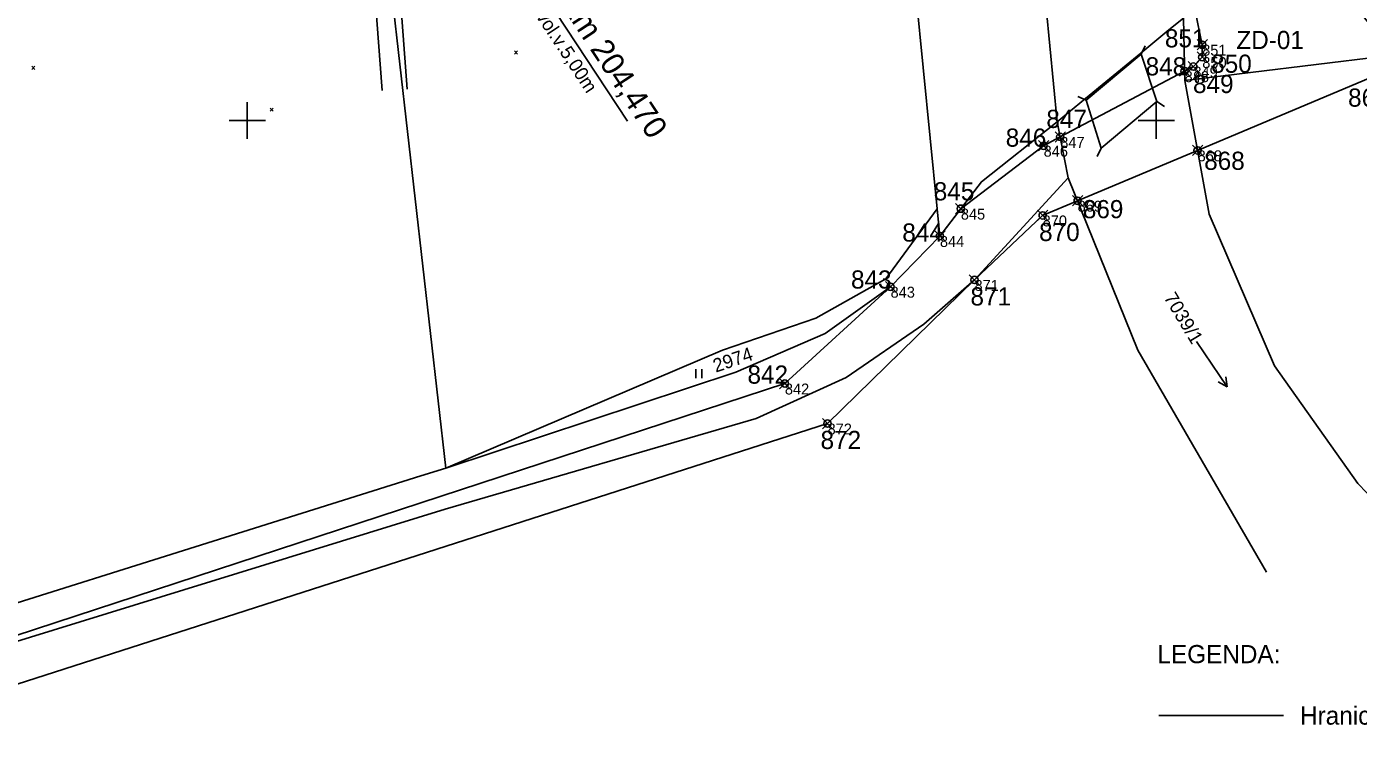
# Model space of a CAD drawing. Extents: x -800194 to -799078, y -1007177 to -1006597.
# Drawn here: x -799524.3 to -799377.8, y -1007068 to -1006989.7 of the extents above; entities that cross this region are included whole.
import ezdxf

# ---------------------------------------------------------------- set-up
doc = ezdxf.new("R2010")
doc.units = 0
for name, color, linetype in [('02_Osa_koleje', 7, 'Continuous'), ('Dočasné zábory', 7, 'Continuous'), ('Dočasné zábory - čísla', 7, 'Continuous'), ('Legenda', 7, 'Continuous'), ('Ramove udaje', 7, 'Continuous'), ('Vrstva 18', 7, 'Continuous'), ('Vrstva 49', 7, 'Continuous'), ('Vrstva 51', 7, 'Continuous'), ('Vrstva 53', 7, 'Continuous'), ('Vrstva 55', 7, 'Continuous'), ('Vrstva 56', 7, 'Continuous'), ('Vrstva 57', 7, 'Continuous'), ('Vrstva 58', 7, 'Continuous'), ('Vrstva 60', 7, 'Continuous')]:
    doc.layers.add(name, color=color, linetype=linetype)

msp = doc.modelspace()

# ---------------------------------------------------------------- linework, layer by layer
at = {"layer": '02_Osa_koleje'}
msp.add_arc((-799651.02, -1006703.89), 292, 255.6249, 308.2052, dxfattribs=at)
at = {"layer": 'Dočasné zábory'}
for p, q in [((-799395.51, -1006992.22), (-799394.38, -1006991.09)), ((-799395.51, -1006991.09), (-799394.38, -1006992.22)), ((-799395.51, -1006993.59), (-799394.37, -1006992.46)), ((-799395.51, -1006992.46), (-799394.37, -1006993.59)), ((-799397.45, -1006995.14), (-799396.32, -1006994.01)), ((-799397.45, -1006994.01), (-799396.32, -1006995.14)), ((-799396.49, -1006994.64), (-799395.36, -1006993.51)), ((-799396.49, -1006993.51), (-799395.36, -1006994.64)), ((-799411.13, -1007002.37), (-799410, -1007001.24)), ((-799411.13, -1007001.24), (-799410, -1007002.37)), ((-799412.96, -1007003.34), (-799411.83, -1007002.21)), ((-799412.96, -1007002.21), (-799411.83, -1007003.34)), ((-799396.02, -1007003.85), (-799394.89, -1007002.72)), ((-799396.02, -1007002.72), (-799394.89, -1007003.85)), ((-799409.22, -1007009.4), (-799408.09, -1007008.26)), ((-799409.22, -1007008.26), (-799408.09, -1007009.4)), ((-799422.07, -1007010.27), (-799420.94, -1007009.14)), ((-799422.07, -1007009.14), (-799420.94, -1007010.27)), ((-799413.06, -1007011.01), (-799411.93, -1007009.88)), ((-799413.06, -1007009.88), (-799411.93, -1007011.01)), ((-799424.37, -1007013.28), (-799423.23, -1007012.14)), ((-799424.37, -1007012.14), (-799423.23, -1007013.28)), ((-799429.8, -1007018.86), (-799428.66, -1007017.72)), ((-799429.8, -1007017.72), (-799428.66, -1007018.86)), ((-799420.57, -1007018.11), (-799419.43, -1007016.97)), ((-799420.57, -1007016.97), (-799419.43, -1007018.11)), ((-799441.43, -1007029.5), (-799440.29, -1007028.37)), ((-799441.43, -1007028.37), (-799440.29, -1007029.5)), ((-799436.73, -1007033.91), (-799435.6, -1007032.78)), ((-799436.73, -1007032.78), (-799435.6, -1007033.91))]:
    msp.add_line(p, q, dxfattribs=at)
for points in [[(-799409.79, -1006894.08), (-799409.48, -1006895.36), (-799407.32, -1006903.81), (-799399.52, -1006945.6), (-799393.3, -1006959.22), (-799387.62, -1006968.78), (-799386.5, -1006977.04), (-799373.97, -1006992.55), (-799373.81, -1006993.12), (-799373.66, -1006993.66), (-799374.58, -1006994.49), (-799377.09, -1006995.58), (-799395.45, -1007003.29), (-799408.65, -1007008.83)], [(-799551.8, -1007065.45), (-799550.16, -1007064.74), (-799440.86, -1007028.94), (-799429.23, -1007018.29), (-799423.8, -1007012.71), (-799421.5, -1007009.7), (-799412.39, -1007002.78), (-799410.56, -1007001.81), (-799396.88, -1006994.58), (-799395.92, -1006994.07), (-799394.94, -1006993.03), (-799394.95, -1006991.66), (-799395.98, -1006986.65), (-799406.07, -1006937.82), (-799408.05, -1006924.38), (-799411.99, -1006900.28), (-799413.45, -1006897.92)], [(-799408.65, -1007008.83), (-799412.5, -1007010.44), (-799420, -1007017.54), (-799436.16, -1007033.34), (-799548.49, -1007069.46), (-799592.16, -1007088.85), (-799605.02, -1007095.33)]]:
    msp.add_lwpolyline(points, dxfattribs=at)
for centre in [(-799394.95, -1006991.66), (-799394.94, -1006993.03), (-799396.88, -1006994.58), (-799395.92, -1006994.07), (-799410.56, -1007001.81), (-799412.39, -1007002.78), (-799395.45, -1007003.29), (-799408.65, -1007008.83), (-799421.5, -1007009.7), (-799412.5, -1007010.44), (-799423.8, -1007012.71), (-799420, -1007017.54), (-799429.23, -1007018.29), (-799440.86, -1007028.94), (-799436.16, -1007033.34)]:
    msp.add_circle(centre, 0.4, dxfattribs=at)
at = {"layer": 'Ramove udaje'}
for p, q in [((-799500, -1006998), (-799500, -1007002)), ((-799400, -1006998), (-799400, -1007002)), ((-799502, -1007000), (-799500, -1007000)), ((-799500, -1007000), (-799498, -1007000)), ((-799402, -1007000), (-799400, -1007000)), ((-799400, -1007000), (-799398, -1007000))]:
    msp.add_line(p, q, dxfattribs=at)
at = {"layer": 'Vrstva 18'}
msp.add_line((-799458.17, -1007000.07), (-799490.2, -1006951.4), dxfattribs=at)
at = {"layer": 'Vrstva 49'}
for p, q in [((-799470.61, -1006992.35), (-799470.26, -1006992.71)), ((-799470.61, -1006992.71), (-799470.26, -1006992.35)), ((-799523.7, -1006994.02), (-799523.35, -1006994.38)), ((-799523.7, -1006994.38), (-799523.35, -1006994.02)), ((-799497.49, -1006998.64), (-799497.14, -1006998.99)), ((-799497.49, -1006998.99), (-799497.14, -1006998.64))]:
    msp.add_line(p, q, dxfattribs=at)
at = {"layer": 'Vrstva 51'}
for points in [[(-799485.17, -1006996.71), (-799487.28, -1006968.61)], [(-799482.42, -1006996.56), (-799484.49, -1006968.49)]]:
    msp.add_lwpolyline(points, dxfattribs=at)
at = {"layer": 'Vrstva 53'}
msp.add_line((-799399.72, -1007065.46), (-799386.02, -1007065.46), dxfattribs=at)
at = {"layer": 'Vrstva 55'}
for p, q in [((-799424.1, -1007009.73), (-799433.4, -1006916.39)), ((-799487.22, -1006958.47), (-799478.14, -1007038.23)), ((-799397.01, -1006988.73), (-799398.6, -1006990.04)), ((-799397.01, -1006988.73), (-799396.86, -1006995.59)), ((-799409.68, -1007006.29), (-799410.89, -1007000.14)), ((-799424.1, -1007009.73), (-799423.8, -1007012.71))]:
    msp.add_line(p, q, dxfattribs=at)
for points in [[(-799410.89, -1007000.14), (-799412.5, -1006983.38), (-799423.07, -1006906.83)], [(-799398.6, -1006990.04), (-799401.7, -1006992.59), (-799402.52, -1006993.26), (-799407.79, -1006997.59), (-799410.89, -1007000.14)], [(-799312.4, -1007006.62), (-799318.99, -1007006.15), (-799364.52, -1006994.13), (-799375.17, -1006992.97), (-799396.86, -1006995.59)], [(-799396.86, -1006995.59), (-799394.17, -1007010.32), (-799387.01, -1007026.98), (-799377.82, -1007039.94), (-799372.89, -1007045.05)], [(-799423.8, -1007012.71), (-799419.24, -1007006.74), (-799410.89, -1007000.14)], [(-799409.68, -1007006.29), (-799420, -1007017.54), (-799425.58, -1007022.42), (-799434.1, -1007028.26), (-799444.02, -1007032.78), (-799478.24, -1007042.75), (-799552.64, -1007065.71), (-799567.11, -1007070.01), (-799588.9, -1007077.33), (-799598.09, -1007080.87), (-799606.31, -1007085.7)], [(-799387.89, -1007049.68), (-799402.01, -1007025.25), (-799409.68, -1007006.29)], [(-799478.14, -1007038.23), (-799447.72, -1007025.26), (-799437.44, -1007021.73), (-799429.75, -1007017.42), (-799424.1, -1007009.73)], [(-799478.14, -1007038.23), (-799446.24, -1007027.7), (-799436.41, -1007023.44), (-799429.23, -1007018.29), (-799423.8, -1007012.71)], [(-799584.37, -1007069.36), (-799568.78, -1007065.44), (-799553.44, -1007061.89), (-799480.9, -1007039.1), (-799478.14, -1007038.23)]]:
    msp.add_lwpolyline(points, dxfattribs=at)
at = {"layer": 'Vrstva 56'}
for p, q in [((-799401.66, -1006992.7), (-799407.73, -1006997.77)), ((-799401.22, -1006991.8), (-799401.66, -1006992.7)), ((-799401.66, -1006992.7), (-799399.93, -1006997.9)), ((-799408.64, -1006997.35), (-799407.73, -1006997.77)), ((-799407.73, -1006997.77), (-799406.07, -1007003.06)), ((-799399.93, -1006997.9), (-799406.07, -1007003.06)), ((-799399.1, -1006998.46), (-799399.93, -1006997.9)), ((-799406.49, -1007003.97), (-799406.07, -1007003.06))]:
    msp.add_line(p, q, dxfattribs=at)
at = {"layer": 'Vrstva 58'}
for p, q in [((-799395.57, -1007024.31), (-799392.21, -1007029.28)), ((-799450.66, -1007028.34), (-799450.66, -1007027.34)), ((-799449.99, -1007028.34), (-799449.99, -1007027.34)), ((-799392.21, -1007029.28), (-799393.18, -1007028.75)), ((-799392.21, -1007029.28), (-799392.35, -1007028.19))]:
    msp.add_line(p, q, dxfattribs=at)
at = {"layer": 'Vrstva 60'}
for p, q in [((-799394.95, -1006991.66), (-799394.95, -1006991.66)), ((-799395.92, -1006994.07), (-799395.92, -1006994.07)), ((-799394.94, -1006993.03), (-799394.94, -1006993.03)), ((-799396.88, -1006994.58), (-799396.88, -1006994.58)), ((-799412.39, -1007002.78), (-799412.39, -1007002.78)), ((-799410.56, -1007001.81), (-799410.56, -1007001.81)), ((-799395.45, -1007003.29), (-799395.45, -1007003.29)), ((-799408.65, -1007008.83), (-799408.65, -1007008.83)), ((-799421.5, -1007009.7), (-799421.5, -1007009.7)), ((-799412.5, -1007010.45), (-799412.5, -1007010.45)), ((-799423.8, -1007012.71), (-799423.8, -1007012.71)), ((-799420, -1007017.54), (-799420, -1007017.54)), ((-799429.23, -1007018.29), (-799429.23, -1007018.29)), ((-799440.86, -1007028.94), (-799440.86, -1007028.94)), ((-799436.16, -1007033.34), (-799436.16, -1007033.34))]:
    msp.add_line(p, q, dxfattribs=at)

# ---------------------------------------------------------------- texts
at = {"layer": 'Dočasné zábory'}
for s, p in [('851', (-799399.05, -1006991.96)), ('850', (-799393.96, -1006994.75)), ('848', (-799401.17, -1006995.04)), ('849', (-799395.96, -1006996.98)), ('867', (-799378.9, -1006998.48)), ('847', (-799412.09, -1007000.82)), ('846', (-799416.56, -1007002.88)), ('868', (-799394.73, -1007005.43)), ('845', (-799424.48, -1007008.79)), ('869', (-799408.08, -1007010.75)), ('844', (-799427.94, -1007013.32)), ('870', (-799412.89, -1007013.26)), ('843', (-799433.58, -1007018.49)), ('871', (-799420.44, -1007020.35)), ('842', (-799444.97, -1007028.95)), ('872', (-799436.93, -1007036.14))]:
    msp.add_text(s, height=2, rotation=360, dxfattribs=at).set_placement(p)
at = {"layer": 'Dočasné zábory - čísla'}
msp.add_text('ZD-01', height=2, rotation=0, dxfattribs=at).set_placement((-799391.19, -1006992.14))
at = {"layer": 'Legenda'}
for s, p in [('LEGENDA:', (-799399.87, -1007059.7)), ('Hranice drážního pozemku', (-799384.18, -1007066.46))]:
    msp.add_text(s, height=2, rotation=360, dxfattribs=at).set_placement(p)
at = {"layer": 'Vrstva 18'}
for s, height, p in [('sv.kol.3,80m vol.v.5,00m', 1.5, (-799474.77, -1006978.68)), ('evid. km 204,470', 2.5, (-799469.71, -1006980.95))]:
    msp.add_text(s, height=height, rotation=303.3554, dxfattribs=at).set_placement(p)
at = {"layer": 'Vrstva 57'}
for s, rotation, p in [('7039/1', 301, (-799399.22, -1007019.47)), ('2974', 19, (-799448.46, -1007027.75))]:
    msp.add_text(s, height=1.5, rotation=rotation, dxfattribs=at).set_placement(p)
at = {"layer": 'Vrstva 60'}
for s, p in [('851', (-799394.95, -1006992.86)), ('849', (-799395.92, -1006995.27)), ('850', (-799394.94, -1006994.23)), ('848', (-799396.88, -1006995.78)), ('846', (-799412.39, -1007003.98)), ('847', (-799410.56, -1007003.01)), ('868', (-799395.45, -1007004.49)), ('869', (-799408.65, -1007010.03)), ('845', (-799421.5, -1007010.9)), ('870', (-799412.5, -1007011.65)), ('844', (-799423.8, -1007013.91)), ('871', (-799420, -1007018.74)), ('843', (-799429.23, -1007019.49)), ('842', (-799440.86, -1007030.14)), ('872', (-799436.16, -1007034.54))]:
    msp.add_text(s, height=1.2, dxfattribs=at).set_placement(p)

doc.saveas('drawing.dxf')
